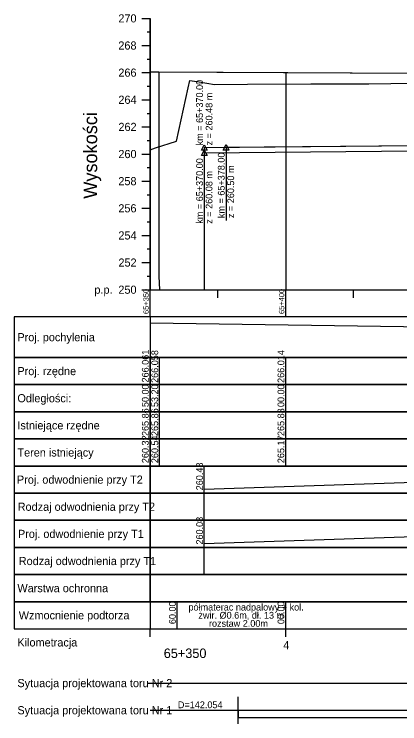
# Model space of a CAD drawing. Extents: x 6531046 to 6533341, y 5514966 to 5518007.
# Drawn here: x 6531046 to 6531188.1, y 5517263.1 to 5517524.6 of the extents above; entities that cross this region are included whole.
import ezdxf

# ---------------------------------------------------------------- set-up
doc = ezdxf.new("R2010")
doc.units = 0
for name, color, linetype in [('IR_default', 7, 'Continuous'), ('TOR_PROF-drenokolektory', 7, 'Continuous'), ('TOR_PROF-opisy pomocnicze', 7, 'Continuous'), ('TOR_PROF-rowy otwarte', 7, 'Continuous'), ('TOR_PROF-tabelka-geometria T1', 7, 'Continuous'), ('TOR_PROF-tabelka-kilometracja', 7, 'Continuous'), ('TOR_PROF-tabelka-odleglosci T1', 7, 'Continuous'), ('TOR_PROF-tabelka-pochylenia proj T1', 7, 'Continuous'), ('TOR_PROF-tabelka-rodzaj rowu T1', 7, 'Continuous'), ('TOR_PROF-tabelka-rowyT1', 7, 'Continuous'), ('TOR_PROF-tabelka-rzedne proj T1', 7, 'Continuous'), ('TOR_PROF-tabelka-teren istniejacy T1', 7, 'Continuous'), ('TOR_PROF-tabelka-warstwa ochronna T1', 7, 'Continuous'), ('TOR_PROF-tor projektowany', 7, 'Continuous'), ('TOR_PROF-uklad odniesienia', 7, 'Continuous'), ('TOR_PROF-warstwa ochronna', 7, 'Continuous'), ('TOR_PROF-wzocnienia podtorza', 7, 'Continuous')]:
    doc.layers.add(name, color=color, linetype=linetype)

msp = doc.modelspace()

# ---------------------------------------------------------------- linework, layer by layer
at = {"layer": 'IR_default'}
msp.add_lwpolyline([(6531096.02, 5517474.69), (6531098.02, 5517475.43), (6531105.74, 5517477.89), (6531110.09, 5517497.46), (6531110.7, 5517500.19), (6531114.07, 5517499.72), (6531119.79, 5517498.74), (6531131.91, 5517498.87), (6531155.27, 5517498.98), (6531176.64, 5517498.97), (6531192.9, 5517499.17)], dxfattribs=at)
at = {"layer": 'TOR_PROF-drenokolektory'}
msp.add_lwpolyline([(6531096.02, 5517523.1), (6531096.02, 5517428.1), (6531096.02, 5517423.1), (6531096.02, 5517423.1)], dxfattribs=at)
at = {"layer": 'TOR_PROF-opisy pomocnicze'}
for p, q in [((6531116.02, 5517475.5), (6531116.02, 5517448.5)), ((6531124.02, 5517475.58), (6531124.02, 5517448.58)), ((6531116.02, 5517473.5), (6531116.02, 5517446.5))]:
    msp.add_line(p, q, dxfattribs=at)
for points in [[(6531116.02, 5517476.5), (6531117.02, 5517474.5), (6531115.02, 5517474.5)], [(6531116.02, 5517474.5), (6531117.02, 5517472.5), (6531115.02, 5517472.5)], [(6531124.02, 5517476.58), (6531125.02, 5517474.58), (6531123.02, 5517474.58)]]:
    msp.add_lwpolyline(points, close=True, dxfattribs=at)
at = {"layer": 'TOR_PROF-rowy otwarte'}
for p, q in [((6531116.02, 5517475.5), (6531326.02, 5517477.6)), ((6531124.02, 5517475.58), (6531326.02, 5517477.6)), ((6531116.02, 5517473.5), (6531326.02, 5517475.6))]:
    msp.add_line(p, q, dxfattribs=at)
for points in [[(6531096.02, 5517523.1), (6531096.02, 5517428.1), (6531096.02, 5517423.1), (6531096.02, 5517423.1)], [(6531116.02, 5517475.5), (6531116.02, 5517428.1), (6531116.02, 5517423.1), (6531116.02, 5517423.1)], [(6531116.02, 5517473.5), (6531116.02, 5517428.1), (6531116.02, 5517423.1), (6531116.02, 5517423.1)]]:
    msp.add_lwpolyline(points, dxfattribs=at)
at = {"layer": 'TOR_PROF-tabelka-geometria T1'}
for points in [[(6531095.09, 5517278.1), (6533095.09, 5517278.1)], [(6531096.02, 5517278.1), (6533096.02, 5517278.1)], [(6531128.45, 5517263.1), (6531128.45, 5517273.1)], [(6531096.02, 5517268.1), (6531128.45, 5517268.1), (6531128.45, 5517265.43), (6531303.45, 5517265.43), (6531303.45, 5517268.1), (6531392.72, 5517268.1), (6531392.72, 5517270.76), (6531567.73, 5517270.76), (6531567.73, 5517268.1), (6532256.58, 5517268.1)], [(6531096.02, 5517268.1), (6533096.02, 5517268.1)]]:
    msp.add_lwpolyline(points, dxfattribs=at)
at = {"layer": 'TOR_PROF-tabelka-kilometracja'}
for points in [[(6531096.02, 5517295.1), (6531096.02, 5517298.1)], [(6531146.02, 5517295.1), (6531146.02, 5517298.1)]]:
    msp.add_lwpolyline(points, dxfattribs=at)
at = {"layer": 'TOR_PROF-tabelka-odleglosci T1'}
for points in [[(6531096.02, 5517388.1), (6531045.95, 5517388.1), (6531045.95, 5517378.1), (6531096.02, 5517378.1)], [(6531096.02, 5517378.1), (6531096.02, 5517388.1)], [(6531099.52, 5517378.1), (6531099.52, 5517388.1)], [(6531146.02, 5517378.1), (6531146.02, 5517388.1)]]:
    msp.add_lwpolyline(points, dxfattribs=at)
msp.add_lwpolyline([(6531096.02, 5517378.1), (6533096.02, 5517378.1), (6533096.02, 5517388.1), (6531096.02, 5517388.1)], close=True, dxfattribs=at)
at = {"layer": 'TOR_PROF-tabelka-pochylenia proj T1'}
for points in [[(6531096.02, 5517413.1), (6531045.95, 5517413.1), (6531045.95, 5517398.1), (6531096.02, 5517398.1)], [(6531096.02, 5517410.85), (6531826.02, 5517400.35)]]:
    msp.add_lwpolyline(points, dxfattribs=at)
msp.add_lwpolyline([(6531096.02, 5517398.1), (6533096.02, 5517398.1), (6533096.02, 5517413.1), (6531096.02, 5517413.1)], close=True, dxfattribs=at)
at = {"layer": 'TOR_PROF-tabelka-rodzaj rowu T1'}
for points in [[(6531096.02, 5517348.1), (6531045.95, 5517348.1), (6531045.95, 5517338.1), (6531096.02, 5517338.1)], [(6531096.02, 5517338.1), (6531096.02, 5517348.1)], [(6531116.02, 5517338.1), (6531116.02, 5517348.1)], [(6531096.02, 5517328.1), (6531045.95, 5517328.1), (6531045.95, 5517318.1), (6531096.02, 5517318.1)], [(6531096.02, 5517318.1), (6531096.02, 5517328.1)], [(6531116.02, 5517318.1), (6531116.02, 5517328.1)]]:
    msp.add_lwpolyline(points, dxfattribs=at)
for points in [[(6531096.02, 5517338.1), (6533096.02, 5517338.1), (6533096.02, 5517348.1), (6531096.02, 5517348.1)], [(6531096.02, 5517318.1), (6533096.02, 5517318.1), (6533096.02, 5517328.1), (6531096.02, 5517328.1)]]:
    msp.add_lwpolyline(points, close=True, dxfattribs=at)
at = {"layer": 'TOR_PROF-tabelka-rowyT1'}
for points in [[(6531096.02, 5517358.1), (6531045.95, 5517358.1), (6531045.95, 5517348.1), (6531096.02, 5517348.1)], [(6531096.02, 5517348.1), (6531096.02, 5517358.1)], [(6531116.02, 5517348.1), (6531116.02, 5517358.1)], [(6531116.02, 5517349.6), (6531326.02, 5517356.6)], [(6531096.02, 5517338.1), (6531045.95, 5517338.1), (6531045.95, 5517328.1), (6531096.02, 5517328.1)], [(6531096.02, 5517328.1), (6531096.02, 5517338.1)], [(6531116.02, 5517328.1), (6531116.02, 5517338.1)], [(6531116.02, 5517329.6), (6531326.02, 5517336.6)]]:
    msp.add_lwpolyline(points, dxfattribs=at)
for points in [[(6531096.02, 5517348.1), (6533096.02, 5517348.1), (6533096.02, 5517358.1), (6531096.02, 5517358.1)], [(6531096.02, 5517328.1), (6533096.02, 5517328.1), (6533096.02, 5517338.1), (6531096.02, 5517338.1)]]:
    msp.add_lwpolyline(points, close=True, dxfattribs=at)
at = {"layer": 'TOR_PROF-tabelka-rzedne proj T1'}
for points in [[(6531096.02, 5517398.1), (6531045.95, 5517398.1), (6531045.95, 5517388.1), (6531096.02, 5517388.1)], [(6531096.02, 5517388.1), (6531096.02, 5517398.1)], [(6531099.52, 5517388.1), (6531099.52, 5517398.1)], [(6531146.02, 5517388.1), (6531146.02, 5517398.1)]]:
    msp.add_lwpolyline(points, dxfattribs=at)
msp.add_lwpolyline([(6531096.02, 5517388.1), (6533096.02, 5517388.1), (6533096.02, 5517398.1), (6531096.02, 5517398.1)], close=True, dxfattribs=at)
at = {"layer": 'TOR_PROF-tabelka-teren istniejacy T1'}
for points in [[(6531096.02, 5517378.1), (6531045.95, 5517378.1), (6531045.95, 5517368.1), (6531096.02, 5517368.1)], [(6531096.02, 5517368.1), (6531096.02, 5517378.1)], [(6531099.52, 5517368.1), (6531099.52, 5517378.1)], [(6531146.02, 5517368.1), (6531146.02, 5517378.1)], [(6531096.02, 5517368.1), (6531045.95, 5517368.1), (6531045.95, 5517358.1), (6531096.02, 5517358.1)], [(6531096.02, 5517358.1), (6531096.02, 5517368.1)], [(6531099.52, 5517358.1), (6531099.52, 5517368.1)], [(6531146.02, 5517358.1), (6531146.02, 5517368.1)]]:
    msp.add_lwpolyline(points, dxfattribs=at)
for points in [[(6531096.02, 5517368.1), (6533096.02, 5517368.1), (6533096.02, 5517378.1), (6531096.02, 5517378.1)], [(6531096.02, 5517358.1), (6533096.02, 5517358.1), (6533096.02, 5517368.1), (6531096.02, 5517368.1)]]:
    msp.add_lwpolyline(points, close=True, dxfattribs=at)
at = {"layer": 'TOR_PROF-tabelka-warstwa ochronna T1'}
for points in [[(6531096.02, 5517503.4), (6531096.02, 5517428.1), (6531096.02, 5517423.1), (6531096.02, 5517423.1)], [(6531099.22, 5517503.39), (6531099.22, 5517428.1), (6531099.52, 5517423.1), (6531099.52, 5517423.1)], [(6531096.02, 5517318.1), (6531045.95, 5517318.1), (6531045.95, 5517308.1), (6531096.02, 5517308.1)], [(6531096.02, 5517308.1), (6531096.02, 5517318.1)]]:
    msp.add_lwpolyline(points, dxfattribs=at)
msp.add_lwpolyline([(6531096.02, 5517308.1), (6533096.02, 5517308.1), (6533096.02, 5517318.1), (6531096.02, 5517318.1)], close=True, dxfattribs=at)
at = {"layer": 'TOR_PROF-tor projektowany'}
for p in [(6531096.02, 5517503.4), (6531099.22, 5517503.39)]:
    msp.add_line(p, (6531826.02, 5517499.95), dxfattribs=at)
for points in [[(6531096.02, 5517503.4), (6531096.26, 5517503.4), (6531097.25, 5517503.4), (6531098.24, 5517503.39), (6531099.22, 5517503.39)], [(6531096.02, 5517503.4), (6531096.02, 5517428.1), (6531096.02, 5517423.1), (6531096.02, 5517423.1)], [(6531099.22, 5517503.39), (6531099.22, 5517428.1), (6531099.52, 5517423.1), (6531099.52, 5517423.1)], [(6531146.02, 5517503.17), (6531146.02, 5517428.1), (6531146.02, 5517423.1), (6531146.02, 5517423.1)]]:
    msp.add_lwpolyline(points, dxfattribs=at)
at = {"layer": 'TOR_PROF-uklad odniesienia'}
for p, q in [((6531093.02, 5517523.1), (6531096.02, 5517523.1)), ((6531096.02, 5517423.1), (6531096.02, 5517523.1)), ((6531095.02, 5517518.1), (6531096.02, 5517518.1)), ((6531093.02, 5517513.1), (6531096.02, 5517513.1)), ((6531095.02, 5517508.1), (6531096.02, 5517508.1)), ((6531093.02, 5517503.1), (6531096.02, 5517503.1)), ((6531095.02, 5517498.1), (6531096.02, 5517498.1)), ((6531093.02, 5517493.1), (6531096.02, 5517493.1)), ((6531095.02, 5517488.1), (6531096.02, 5517488.1)), ((6531093.02, 5517483.1), (6531096.02, 5517483.1)), ((6531095.02, 5517478.1), (6531096.02, 5517478.1)), ((6531093.02, 5517473.1), (6531096.02, 5517473.1)), ((6531095.02, 5517468.1), (6531096.02, 5517468.1)), ((6531093.02, 5517463.1), (6531096.02, 5517463.1)), ((6531095.02, 5517458.1), (6531096.02, 5517458.1)), ((6531093.02, 5517453.1), (6531096.02, 5517453.1)), ((6531095.02, 5517448.1), (6531096.02, 5517448.1)), ((6531093.02, 5517443.1), (6531096.02, 5517443.1)), ((6531095.02, 5517438.1), (6531096.02, 5517438.1)), ((6531093.02, 5517433.1), (6531096.02, 5517433.1)), ((6531095.02, 5517428.1), (6531096.02, 5517428.1)), ((6531093.02, 5517423.1), (6531096.02, 5517423.1)), ((6531096.02, 5517423.1), (6533096.02, 5517423.1)), ((6531096.02, 5517413.1), (6531096.02, 5517423.1)), ((6531121.02, 5517420.1), (6531121.02, 5517423.1)), ((6531146.02, 5517413.1), (6531146.02, 5517423.1)), ((6531171.02, 5517420.1), (6531171.02, 5517423.1))]:
    msp.add_line(p, q, dxfattribs=at)
at = {"layer": 'TOR_PROF-warstwa ochronna'}
for points in [[(6531106.02, 5517298.1), (6531106.02, 5517308.1)], [(6531146.02, 5517298.1), (6531146.02, 5517308.1)]]:
    msp.add_lwpolyline(points, dxfattribs=at)
at = {"layer": 'TOR_PROF-wzocnienia podtorza'}
msp.add_lwpolyline([(6531096.02, 5517308.1), (6531045.95, 5517308.1), (6531045.95, 5517298.1), (6531096.02, 5517298.1)], dxfattribs=at)
msp.add_lwpolyline([(6531096.02, 5517298.1), (6533096.02, 5517298.1), (6533096.02, 5517308.1), (6531096.02, 5517308.1)], close=True, dxfattribs=at)

# ---------------------------------------------------------------- texts
at = {"layer": 'TOR_PROF-opisy pomocnicze'}
for s, p in [('km = 65+370.00', (6531115.52, 5517476.28)), ('z = 260.48 m', (6531119.02, 5517476.28)), ('km = 65+370.00', (6531115.52, 5517447.4)), ('km = 65+378.00', (6531123.52, 5517449.48)), ('z = 260.08 m', (6531119.02, 5517447.4)), ('z = 260.50 m', (6531127.02, 5517449.48))]:
    msp.add_text(s, height=2.5, rotation=90, dxfattribs=at).set_placement(p)
at = {"layer": 'TOR_PROF-tabelka-geometria T1'}
for s, height, p in [(' Sytuacja projektowana toru Nr 2', 3, (6531046.02, 5517276.6)), ('D=142.054', 2.5, (6531106.28, 5517268.85)), (' Sytuacja projektowana toru Nr 1 ', 3, (6531046.02, 5517266.6))]:
    msp.add_text(s, height=height, dxfattribs=at).set_placement(p)
at = {"layer": 'TOR_PROF-tabelka-kilometracja'}
for s, p in [(' Kilometracja ', (6531046.02, 5517291.6)), ('4', (6531145.13, 5517290.6))]:
    msp.add_text(s, height=3, dxfattribs=at).set_placement(p)
msp.add_text('65+350', height=3.5, rotation=360, dxfattribs=at).set_placement((6531101.07, 5517287.35))
at = {"layer": 'TOR_PROF-tabelka-odleglosci T1'}
for s, p in [('50.00', (6531095.52, 5517379.84)), ('53.20', (6531099.02, 5517379.84)), ('00.00', (6531145.52, 5517379.84))]:
    msp.add_text(s, height=2.5, rotation=90, dxfattribs=at).set_placement(p)
msp.add_text(' Odległości: ', height=3, dxfattribs=at).set_placement((6531046.02, 5517381.6))
at = {"layer": 'TOR_PROF-tabelka-pochylenia proj T1'}
msp.add_text(' Proj. pochylenia', height=3, dxfattribs=at).set_placement((6531046.02, 5517404.1))
at = {"layer": 'TOR_PROF-tabelka-rodzaj rowu T1'}
for s, p in [(' Rodzaj odwodnienia przy T2 ', (6531046.13, 5517341.6)), (' Rodzaj odwodnienia przy T1 ', (6531046.52, 5517321.6))]:
    msp.add_text(s, height=3, dxfattribs=at).set_placement(p)
at = {"layer": 'TOR_PROF-tabelka-rowyT1'}
for s, p in [('260.48', (6531115.52, 5517349.16)), ('260.08', (6531115.52, 5517329.16))]:
    msp.add_text(s, height=2.5, rotation=90, dxfattribs=at).set_placement(p)
for s, p in [(' Proj. odwodnienie przy T2 ', (6531045.84, 5517351.6)), (' Proj. odwodnienie przy T1 ', (6531046.22, 5517331.6))]:
    msp.add_text(s, height=3, dxfattribs=at).set_placement(p)
at = {"layer": 'TOR_PROF-tabelka-rzedne proj T1'}
for s, p in [('266.061', (6531095.52, 5517388.9)), ('266.058', (6531099.02, 5517388.73)), ('266.014', (6531145.52, 5517388.74))]:
    msp.add_text(s, height=2.5, rotation=90, dxfattribs=at).set_placement(p)
msp.add_text(' Proj. rzędne', height=3, dxfattribs=at).set_placement((6531046.02, 5517391.6))
at = {"layer": 'TOR_PROF-tabelka-teren istniejacy T1'}
for s, p in [('265.86', (6531095.52, 5517369.16)), ('265.86', (6531099.02, 5517369.16)), ('265.83', (6531145.52, 5517369.16)), ('260.32', (6531095.52, 5517359.17)), ('260.54', (6531099.02, 5517359.17)), ('265.17', (6531145.52, 5517359.16))]:
    msp.add_text(s, height=2.5, rotation=90, dxfattribs=at).set_placement(p)
for s, p in [(' Istniejące rzędne', (6531046.02, 5517371.6)), (' Teren istniejący', (6531046.02, 5517361.6))]:
    msp.add_text(s, height=3, dxfattribs=at).set_placement(p)
at = {"layer": 'TOR_PROF-tabelka-warstwa ochronna T1'}
msp.add_text(' Warstwa ochronna ', height=3, dxfattribs=at).set_placement((6531046.02, 5517311.6))
at = {"layer": 'TOR_PROF-uklad odniesienia'}
for s, height, p in [('270', 3, (6531084.35, 5517521.6)), ('268', 3, (6531084.34, 5517511.6)), ('266', 3, (6531084.34, 5517501.6)), ('264', 3, (6531084.36, 5517491.6)), ('262', 3, (6531084.38, 5517481.6)), ('260', 3, (6531084.35, 5517471.6)), ('258', 3, (6531084.34, 5517461.6)), ('256', 3, (6531084.34, 5517451.6)), ('254', 3, (6531084.36, 5517441.6)), ('252', 3, (6531084.38, 5517431.6)), ('250', 3, (6531084.35, 5517421.6)), ('p.p.', 3, (6531075.51, 5517421.6)), ('-', 0.0001, (6531096.02, 5517423.1))]:
    msp.add_text(s, height=height, dxfattribs=at).set_placement(p)
for s, height, p in [('Wysokości', 5, (6531076.52, 5517456.62)), ('65+350', 2, (6531095.52, 5517414.12)), ('65+400', 2, (6531145.52, 5517414.12))]:
    msp.add_text(s, height=height, rotation=90, dxfattribs=at).set_placement(p)
at = {"layer": 'TOR_PROF-warstwa ochronna'}
for s, rotation, p in [('60.00', 90, (6531105.52, 5517299.84)), ('półmaterac nadpalowy + kol.', 360, (6531110.19, 5517304.85)), ('00.00', 90, (6531145.52, 5517299.84)), ('żwir. Ø0.6m, dł. 13 m, ', 360, (6531113.85, 5517301.85)), ('rozstaw 2.00m', 360, (6531117.74, 5517298.85))]:
    msp.add_text(s, height=2.5, rotation=rotation, dxfattribs=at).set_placement(p)
msp.add_text(' Wzmocnienie podtorza', height=3, dxfattribs=at).set_placement((6531046.52, 5517301.6))

doc.saveas('drawing.dxf')
